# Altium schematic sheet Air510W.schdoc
size 127 x 99 mm
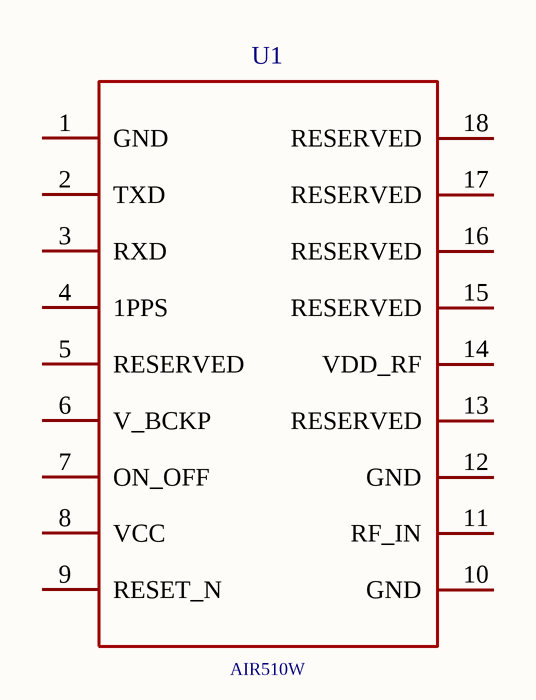
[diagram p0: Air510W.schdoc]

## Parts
U1  AIR510W

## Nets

Not connected (* = marked no-connect by the designer): U1 1(GND) 2(TXD) 3(RXD) 4(1PPS) 5(RESERVED) 6(V_BCKP) 7(ON_OFF) 8(VCC) 9(RESET_N) 10(GND) 11(RF_IN) 12(GND) 13(RESERVED) 14(VDD_RF) 15(RESERVED) 16(RESERVED) 17(RESERVED) 18(RESERVED)

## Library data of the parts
U1 = AIR510W: Add into BOM: yes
